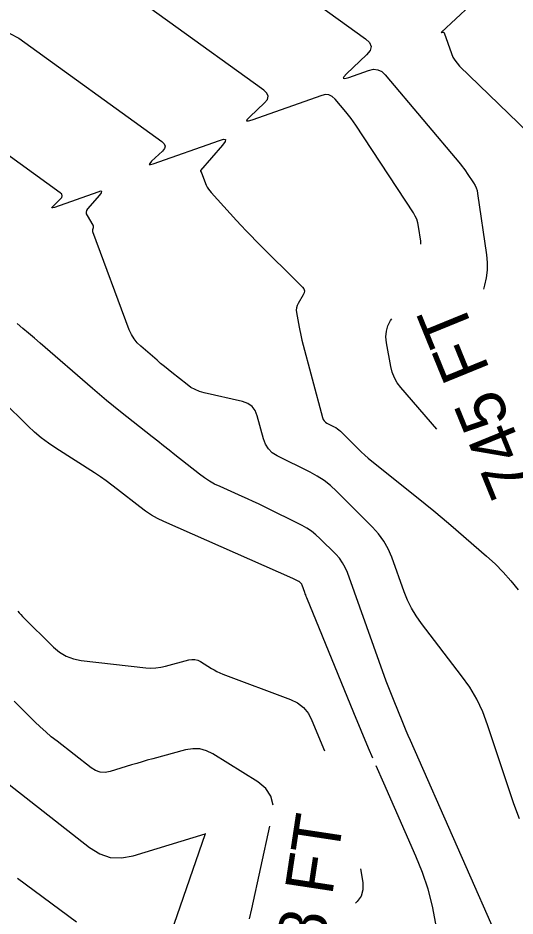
# Model space of a CAD drawing. Extents: x 1354696 to 1366163, y 660729 to 670380.
# Drawn here: x 1361011.4 to 1361073.5, y 664701.2 to 664813.3 of the extents above; entities that cross this region are included whole.
import ezdxf

# ---------------------------------------------------------------- set-up
doc = ezdxf.new("R2010")
doc.units = 0
doc.layers.add('R_Contour Annot', color=7, linetype='Continuous')
doc.layers.add('R_Contours', color=7, linetype='Continuous')

msp = doc.modelspace()

# ---------------------------------------------------------------- linework, layer by layer
at = {"layer": 'R_Contours'}
for points in [[(1361030.93, 664827.91), (1361054.82, 664810.69), (1361055.31, 664810.22), (1361055.5, 664809.73), (1361055.38, 664809.21), (1361054.95, 664808.68), (1361052.43, 664806.33), (1361052.09, 664805.96), (1361052.02, 664805.76), (1361052.23, 664805.73), (1361052.71, 664805.87), (1361055.19, 664806.75), (1361055.79, 664806.88), (1361056.33, 664806.83), (1361056.83, 664806.6), (1361057.28, 664806.18), (1361066.66, 664795.04), (1361066.89, 664794.76), (1361067.11, 664794.48), (1361067.32, 664794.19), (1361067.52, 664793.89), (1361068.31, 664792.69), (1361068.49, 664792.39), (1361068.63, 664792.07), (1361068.74, 664791.73), (1361068.8, 664791.38), (1361069.92, 664783.7), (1361070, 664782.74), (1361069.99, 664781.79), (1361069.88, 664780.84), (1361069.67, 664779.91), (1361069.54, 664779.42)], [(1361061.74, 664785.07), (1361061.71, 664785.42), (1361061.44, 664787.26), (1361061.35, 664787.72), (1361061.21, 664788.15), (1361061.03, 664788.56), (1361060.8, 664788.96), (1361053.6, 664799.89), (1361053.31, 664800.33), (1361053, 664800.75), (1361052.68, 664801.16), (1361052.35, 664801.57), (1361051.01, 664803.17), (1361050.65, 664803.5), (1361050.25, 664803.68), (1361049.82, 664803.72), (1361049.35, 664803.62), (1361040.63, 664800.52), (1361040.17, 664800.39), (1361039.97, 664800.42), (1361040.04, 664800.61), (1361040.37, 664800.96), (1361042.21, 664802.68), (1361042.55, 664803.11), (1361042.64, 664803.52), (1361042.5, 664803.91), (1361042.11, 664804.28), (1361018.04, 664821.63)], [(1361067.87, 664814.85), (1361064.3, 664811.5), (1361064.27, 664811.48), (1361064.27, 664811.46), (1361064.28, 664811.46), (1361064.32, 664811.46), (1361064.51, 664811.51), (1361064.55, 664811.52), (1361064.59, 664811.51), (1361064.61, 664811.48), (1361064.63, 664811.45), (1361065.55, 664808.85), (1361065.73, 664808.41), (1361065.96, 664808.01), (1361066.24, 664807.63), (1361066.55, 664807.29), (1361076.37, 664797.8)], [(1361010.4, 664811.37), (1361011.51, 664810.76), (1361029.39, 664797.87), (1361029.68, 664797.59), (1361029.79, 664797.3), (1361029.72, 664797), (1361029.47, 664796.68), (1361028.1, 664795.4), (1361027.86, 664795.14), (1361027.81, 664795), (1361027.95, 664794.98), (1361028.3, 664795.08), (1361036.56, 664798.01), (1361037.08, 664798.15), (1361037.33, 664798.1), (1361037.29, 664797.86), (1361036.97, 664797.42), (1361034.22, 664794.24), (1361034.21, 664794.21), (1361034.2, 664794.19), (1361034.2, 664794.17), (1361034.21, 664794.15), (1361034.27, 664794.05), (1361034.28, 664794.03), (1361034.3, 664794), (1361034.31, 664793.98), (1361034.32, 664793.95), (1361034.93, 664792.43), (1361035.05, 664792.18), (1361035.19, 664791.93), (1361035.35, 664791.71), (1361035.53, 664791.49), (1361038.7, 664788.01), (1361039.29, 664787.36), (1361039.89, 664786.72), (1361040.51, 664786.09), (1361041.12, 664785.47), (1361046.93, 664779.69), (1361047.1, 664779.46), (1361047.18, 664779.23), (1361047.16, 664778.98), (1361047.04, 664778.72), (1361046.4, 664777.65), (1361046.26, 664777.38), (1361046.18, 664777.1), (1361046.15, 664776.81), (1361046.18, 664776.51), (1361046.51, 664774.69), (1361046.59, 664774.28), (1361046.68, 664773.88), (1361046.77, 664773.48), (1361046.87, 664773.08), (1361049.43, 664763.39), (1361049.51, 664763.17), (1361049.63, 664762.98), (1361049.8, 664762.82), (1361050, 664762.7), (1361050.88, 664762.25), (1361051.1, 664762.14), (1361051.3, 664762), (1361051.49, 664761.85), (1361051.68, 664761.69), (1361053.85, 664759.52), (1361054.27, 664759.11), (1361054.71, 664758.71), (1361055.16, 664758.32), (1361055.62, 664757.95), (1361061.19, 664753.51), (1361062.27, 664752.65), (1361063.34, 664751.77), (1361064.4, 664750.88), (1361065.45, 664749.98), (1361069.92, 664746.09), (1361070.99, 664745.12), (1361072.01, 664744.09), (1361072.97, 664743.02), (1361073.88, 664741.9)], [(1361074.03, 664713.3), (1361073.35, 664715.16), (1361072.7, 664717.05), (1361070.06, 664725.05), (1361069.45, 664726.68), (1361068.7, 664728.24), (1361067.83, 664729.74), (1361066.82, 664731.16), (1361061.79, 664737.7), (1361061.13, 664738.63), (1361060.55, 664739.6), (1361060.05, 664740.61), (1361059.62, 664741.66), (1361058.08, 664745.97), (1361057.64, 664747.01), (1361057.1, 664747.98), (1361056.44, 664748.89), (1361055.69, 664749.73), (1361051.17, 664754.23), (1361050.42, 664754.91), (1361049.63, 664755.53), (1361048.79, 664756.08), (1361047.91, 664756.57), (1361043.78, 664758.62), (1361043.17, 664759), (1361042.68, 664759.48), (1361042.31, 664760.06), (1361042.06, 664760.74), (1361041.3, 664763.63), (1361041.04, 664764.28), (1361040.65, 664764.8), (1361040.12, 664765.17), (1361039.46, 664765.41), (1361034.65, 664766.5), (1361034.07, 664766.66), (1361033.53, 664766.89), (1361033.01, 664767.17), (1361032.52, 664767.51), (1361030.63, 664769.01), (1361030.16, 664769.39), (1361029.69, 664769.77), (1361029.22, 664770.16), (1361028.77, 664770.55), (1361026.74, 664772.3), (1361026.29, 664772.75), (1361025.9, 664773.24), (1361025.57, 664773.78), (1361025.31, 664774.36), (1361020.77, 664786.59), (1361020.75, 664786.66), (1361020.74, 664786.73), (1361020.74, 664786.8), (1361020.76, 664786.87), (1361020.84, 664787.15), (1361020.85, 664787.22), (1361020.85, 664787.28), (1361020.84, 664787.35), (1361020.81, 664787.41), (1361020.08, 664788.62), (1361019.98, 664788.83), (1361019.96, 664789.04), (1361020.02, 664789.25), (1361020.15, 664789.45), (1361021.63, 664791.16), (1361021.84, 664791.45), (1361021.87, 664791.61), (1361021.71, 664791.65), (1361021.36, 664791.55), (1361015.96, 664789.63), (1361015.74, 664789.57), (1361015.64, 664789.58), (1361015.67, 664789.68), (1361015.83, 664789.85), (1361016.73, 664790.69), (1361016.89, 664790.89), (1361016.94, 664791.09), (1361016.87, 664791.28), (1361016.68, 664791.46), (1361004.99, 664799.89)], [(1361063.7, 664761.97), (1361059.23, 664767.14), (1361058.78, 664767.74), (1361058.42, 664768.37), (1361058.15, 664769.05), (1361057.97, 664769.77), (1361057.43, 664772.75), (1361057.36, 664773.48), (1361057.42, 664774.18), (1361057.62, 664774.86), (1361057.95, 664775.52), (1361058.08, 664775.74)], [(1361072.19, 664696.44), (1361060.42, 664723.09), (1361060.15, 664723.7), (1361059.89, 664724.31), (1361059.63, 664724.93), (1361059.38, 664725.54), (1361058.37, 664728.01), (1361058.12, 664728.63), (1361057.88, 664729.25), (1361057.64, 664729.88), (1361057.41, 664730.5), (1361052.55, 664744.04), (1361052.29, 664744.68), (1361051.95, 664745.27), (1361051.56, 664745.83), (1361051.09, 664746.34), (1361049.11, 664748.31), (1361048.6, 664748.78), (1361048.06, 664749.2), (1361047.48, 664749.58), (1361046.88, 664749.92), (1361042.12, 664752.29), (1361041.44, 664752.62), (1361040.76, 664752.94), (1361040.08, 664753.26), (1361039.4, 664753.56), (1361036.65, 664754.78), (1361035.97, 664755.1), (1361035.32, 664755.47), (1361034.69, 664755.87), (1361034.09, 664756.32), (1361031.01, 664758.76), (1361030.3, 664759.32), (1361029.59, 664759.89), (1361028.88, 664760.45), (1361028.16, 664761.01), (1361024.23, 664764.11), (1361023.35, 664764.82), (1361022.47, 664765.54), (1361021.59, 664766.27), (1361020.73, 664767.01), (1361014.16, 664772.69), (1361013.45, 664773.31), (1361012.73, 664773.92), (1361012.01, 664774.52), (1361011.29, 664775.13)], [(1361055.74, 664720.87), (1361055.19, 664722.13), (1361054.26, 664724.34), (1361053.35, 664726.55), (1361047.48, 664740.91), (1361047.41, 664741.08), (1361047.35, 664741.25), (1361047.28, 664741.41), (1361047.22, 664741.58), (1361046.9, 664742.48), (1361046.87, 664742.54), (1361046.85, 664742.59), (1361046.81, 664742.63), (1361046.77, 664742.68), (1361046.61, 664742.84), (1361046.57, 664742.88), (1361046.52, 664742.92), (1361046.47, 664742.95), (1361046.42, 664742.98), (1361046.06, 664743.15), (1361045.99, 664743.19), (1361045.91, 664743.23), (1361045.83, 664743.27), (1361045.75, 664743.3), (1361029.64, 664750.42), (1361028.85, 664750.8), (1361028.08, 664751.23), (1361027.34, 664751.71), (1361026.63, 664752.24), (1361023.85, 664754.44), (1361023.14, 664754.98), (1361022.43, 664755.51), (1361021.7, 664756.01), (1361020.96, 664756.5), (1361016.13, 664759.56), (1361015.21, 664760.19), (1361014.32, 664760.86), (1361013.47, 664761.57), (1361012.66, 664762.34), (1361009.48, 664765.49)], [(1361011.37, 664739.25), (1361011.56, 664739.02), (1361011.75, 664738.8), (1361011.96, 664738.58), (1361015.85, 664734.74), (1361016.6, 664734.11), (1361017.43, 664733.62), (1361018.32, 664733.28), (1361019.29, 664733.09), (1361027.37, 664732.17), (1361028, 664732.13), (1361028.62, 664732.15), (1361029.24, 664732.23), (1361029.85, 664732.36), (1361032.75, 664733.15), (1361033.13, 664733.21), (1361033.5, 664733.2), (1361033.86, 664733.11), (1361034.2, 664732.94), (1361035.56, 664732.09), (1361035.91, 664731.89), (1361036.26, 664731.7), (1361036.62, 664731.53), (1361036.99, 664731.38), (1361045.44, 664728.2), (1361046.33, 664727.77), (1361047.07, 664727.19), (1361047.67, 664726.47), (1361048.12, 664725.6), (1361049.68, 664721.78)], [(1361043.26, 664714.99), (1361043, 664716.12), (1361042.36, 664717.1), (1361041.35, 664717.93), (1361035.76, 664721.41), (1361034.95, 664721.81), (1361034.11, 664722.03), (1361033.24, 664722.06), (1361032.34, 664721.91), (1361028.23, 664720.8), (1361027.56, 664720.61), (1361026.9, 664720.42), (1361026.24, 664720.23), (1361025.58, 664720.03), (1361022.93, 664719.22), (1361022.29, 664719.1), (1361021.67, 664719.13), (1361021.08, 664719.32), (1361020.53, 664719.67), (1361016.29, 664722.98), (1361015.57, 664723.56), (1361014.87, 664724.16), (1361014.19, 664724.78), (1361013.53, 664725.41), (1361010.91, 664728)], [(1361063.59, 664700.21), (1361063.18, 664702.38), (1361062.63, 664704.51), (1361061.94, 664706.61), (1361061.11, 664708.66), (1361057.1, 664717.74), (1361056.14, 664719.92)], [(1361008.72, 664718.81), (1361020.34, 664709.71), (1361021.61, 664708.93), (1361022.94, 664708.49), (1361024.34, 664708.42), (1361025.81, 664708.7), (1361034.79, 664711.45), (1361034.8, 664711.45), (1361034.8, 664711.45), (1361034.81, 664711.44), (1361034.81, 664711.44), (1361034.81, 664711.44), (1361034.8, 664711.43), (1361034.8, 664711.42), (1361030.08, 664697.84)], [(1361040.31, 664700.83), (1361040.6, 664702.06), (1361042.86, 664712.38)], [(1361054.19, 664707.06), (1361054.46, 664705.34), (1361054.49, 664704.43), (1361054.26, 664703.64), (1361053.78, 664702.97), (1361053.55, 664702.79)], [(1361011.35, 664705.91), (1361018.73, 664700.45)]]:
    msp.add_lwpolyline(points, dxfattribs=at)

# ---------------------------------------------------------------- texts
at = {"layer": 'R_Contour Annot'}
for s, rotation, p in [('745 FT', 112.184, (1361076.29, 664754.91)), ('748 FT', 81.3906, (1361048.3, 664688.19))]:
    msp.add_text(s, height=6, rotation=rotation, dxfattribs=at).set_placement(p)

doc.saveas('drawing.dxf')
